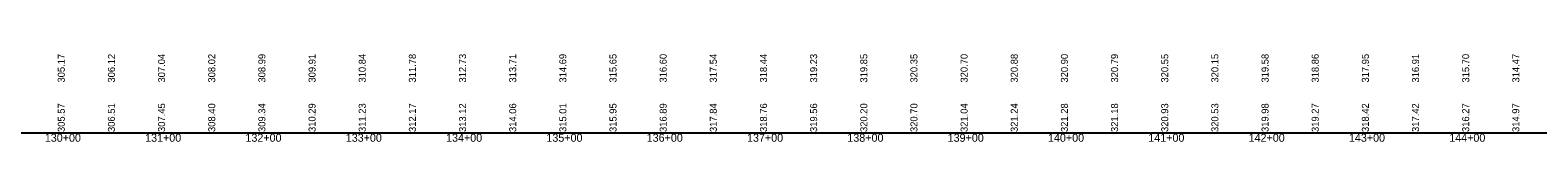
# Model space of a CAD drawing. Extents: x 1876258 to 1926563, y 729739 to 834437.
# Drawn here: x 1891328 to 1892831, y 830495 to 830583 of the extents above; entities that cross this region are included whole.
import ezdxf

# ---------------------------------------------------------------- set-up
doc = ezdxf.new("R2010")
doc.units = 0
for name, color, linetype in [('RD_EX_RailRoad', 7, 'Continuous'), ('RD_PD_ALT3_CL', 7, 'Continuous'), ('RD_PD_Final_Cl', 7, 'Continuous')]:
    doc.layers.add(name, color=color, linetype=linetype)

msp = doc.modelspace()

# ---------------------------------------------------------------- linework, layer by layer
at = {"layer": 'RD_PD_Final_Cl'}
msp.add_line((1878363.1, 830504.3), (1926563.1, 830504.3), dxfattribs=at)

# ---------------------------------------------------------------- texts
at = {"layer": 'RD_EX_RailRoad'}
for s, p in [('305.17', (1891362.1, 830554.3)), ('306.12', (1891412.1, 830554.3)), ('307.04', (1891462.1, 830554.3)), ('308.02', (1891512.1, 830554.3)), ('308.99', (1891562.1, 830554.3)), ('309.91', (1891612.1, 830554.3)), ('310.84', (1891662.1, 830554.3)), ('311.78', (1891712.1, 830554.3)), ('312.73', (1891762.1, 830554.3)), ('313.71', (1891812.1, 830554.3)), ('314.69', (1891862.1, 830554.3)), ('315.65', (1891912.1, 830554.3)), ('316.60', (1891962.1, 830554.3)), ('317.54', (1892012.1, 830554.3)), ('318.44', (1892062.1, 830554.3)), ('319.23', (1892112.1, 830554.3)), ('319.85', (1892162.1, 830554.3)), ('320.35', (1892212.1, 830554.3)), ('320.70', (1892262.1, 830554.3)), ('320.88', (1892312.1, 830554.3)), ('320.90', (1892362.1, 830554.3)), ('320.79', (1892412.1, 830554.3)), ('320.55', (1892462.1, 830554.3)), ('320.15', (1892512.1, 830554.3)), ('319.58', (1892562.1, 830554.3)), ('318.86', (1892612.1, 830554.3)), ('317.95', (1892662.1, 830554.3)), ('316.91', (1892712.1, 830554.3)), ('315.70', (1892762.1, 830554.3)), ('314.47', (1892812.1, 830554.3)), ('305.57', (1891362.1, 830505)), ('306.51', (1891412.1, 830505)), ('307.45', (1891462.1, 830505)), ('308.40', (1891512.1, 830505)), ('309.34', (1891562.1, 830505)), ('310.29', (1891612.1, 830505)), ('311.23', (1891662.1, 830505)), ('312.17', (1891712.1, 830505)), ('313.12', (1891762.1, 830505)), ('314.06', (1891812.1, 830505)), ('315.01', (1891862.1, 830505)), ('315.95', (1891912.1, 830505)), ('316.89', (1891962.1, 830505)), ('317.84', (1892012.1, 830505)), ('318.76', (1892062.1, 830505)), ('319.56', (1892112.1, 830505)), ('320.20', (1892162.1, 830505)), ('320.70', (1892212.1, 830505)), ('321.04', (1892262.1, 830505)), ('321.24', (1892312.1, 830505)), ('321.28', (1892362.1, 830505)), ('321.18', (1892412.1, 830505)), ('320.93', (1892462.1, 830505)), ('320.53', (1892512.1, 830505)), ('319.98', (1892562.1, 830505)), ('319.27', (1892612.1, 830505)), ('318.42', (1892662.1, 830505)), ('317.42', (1892712.1, 830505)), ('316.27', (1892762.1, 830505)), ('314.97', (1892812.1, 830505))]:
    msp.add_text(s, height=7, rotation=90, dxfattribs=at).set_placement(p)
at = {"layer": 'RD_PD_ALT3_CL'}
for s, p in [('130+00', (1891342.2, 830495.3)), ('130+00', (1891342.2, 830495.3)), ('131+00', (1891442.2, 830495.3)), ('131+00', (1891442.2, 830495.3)), ('132+00', (1891542.2, 830495.3)), ('132+00', (1891542.2, 830495.3)), ('133+00', (1891642.2, 830495.3)), ('133+00', (1891642.2, 830495.3)), ('134+00', (1891742.2, 830495.3)), ('134+00', (1891742.2, 830495.3)), ('135+00', (1891842.2, 830495.3)), ('135+00', (1891842.2, 830495.3)), ('136+00', (1891942.2, 830495.3)), ('136+00', (1891942.2, 830495.3)), ('137+00', (1892042.2, 830495.3)), ('137+00', (1892042.2, 830495.3)), ('138+00', (1892142.2, 830495.3)), ('138+00', (1892142.2, 830495.3)), ('139+00', (1892242.2, 830495.3)), ('139+00', (1892242.2, 830495.3)), ('140+00', (1892342.2, 830495.3)), ('140+00', (1892342.2, 830495.3)), ('141+00', (1892442.2, 830495.3)), ('141+00', (1892442.2, 830495.3)), ('142+00', (1892542.2, 830495.3)), ('142+00', (1892542.2, 830495.3)), ('143+00', (1892642.2, 830495.3)), ('143+00', (1892642.2, 830495.3)), ('144+00', (1892742.2, 830495.3)), ('144+00', (1892742.2, 830495.3))]:
    msp.add_text(s, height=8, dxfattribs=at).set_placement(p)

doc.saveas('drawing.dxf')
